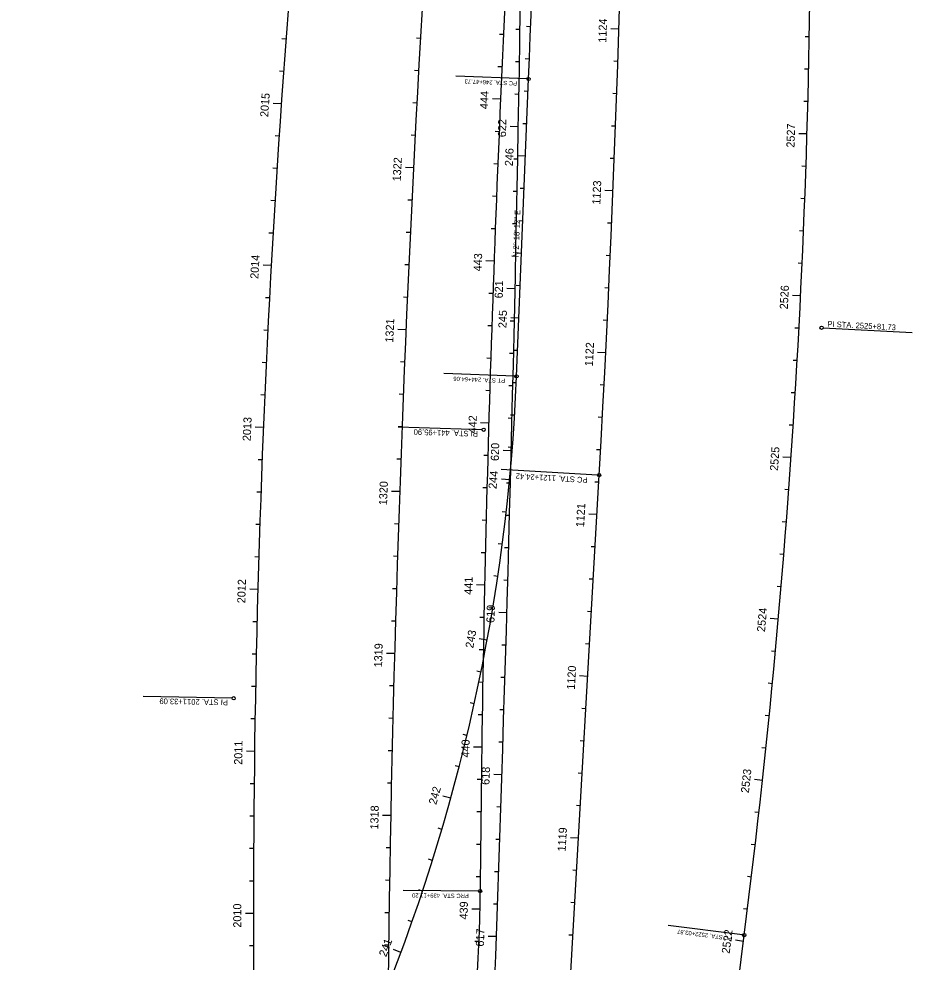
# Model space of a CAD drawing. Extents: x 919452 to 931278, y 583254 to 665650.
# Drawn here: x 928794 to 929346, y 637530 to 638112 of the extents above; entities that cross this region are included whole.
import ezdxf

# ---------------------------------------------------------------- set-up
doc = ezdxf.new("R2010")
doc.units = 0
for name, color, linetype in [('LaneLine', 7, 'Continuous'), ('PMStripe24W', 7, 'Continuous'), ('Scratch1_dp', 7, 'Continuous'), ('ScratchEle_dp', 7, 'Continuous'), ('ShldrHatch', 7, 'Continuous'), ('TollReader', 7, 'Continuous')]:
    doc.layers.add(name, color=color, linetype=linetype)

msp = doc.modelspace()

# ---------------------------------------------------------------- linework, layer by layer
at = {"layer": 'LaneLine'}
for p, q in [((929107.8, 638074.87), (929063.82, 638076.64)), ((929290.62, 637921.24), (929345.52, 637918.33)), ((929100.42, 637891.34), (929056.57, 637893.11)), ((929080.12, 637858.38), (929028.39, 637859.87)), ((929151.39, 637830.41), (929091.99, 637833.78)), ((928925.82, 637692.64), (928870.93, 637693.63)), ((929077.93, 637573.66), (929031.41, 637574.02)), ((929240.92, 637546.59), (929195.04, 637552.42))]:
    msp.add_line(p, q, dxfattribs=at)
for centre in [(929108.8, 638074.83), (929289.62, 637921.3), (929101.42, 637891.3), (929081.12, 637858.35), (929152.38, 637830.35), (928926.82, 637692.63), (929078.93, 637573.66), (929241.91, 637546.46)]:
    msp.add_circle(centre, 1, dxfattribs=at)
at = {"layer": 'Scratch1_dp'}
for p, q in [((929103.52, 638105.32), (929101.02, 638105.36)), ((929110.06, 638107.07), (929107.56, 638107.16)), ((928959.04, 638099.35), (928956.55, 638099.53)), ((929042.08, 638099.86), (929039.58, 638100)), ((929093.34, 638102.23), (929090.84, 638102.35)), ((929282.08, 638100.87), (929279.58, 638100.91)), ((929092.42, 638082.25), (929089.92, 638082.36)), ((929103.19, 638085.32), (929100.69, 638085.36)), ((929109.29, 638087.08), (929106.79, 638087.18)), ((929163.91, 638085.67), (929161.41, 638085.75)), ((928957.58, 638079.4), (928955.09, 638079.58)), ((929040.97, 638079.89), (929038.47, 638080.03)), ((929281.68, 638080.87), (929279.18, 638080.92)), ((929102.85, 638065.32), (929100.35, 638065.37)), ((929108.49, 638067.1), (929105.99, 638067.2)), ((929163.22, 638065.68), (929160.73, 638065.77)), ((929039.88, 638059.92), (929037.39, 638060.05)), ((929281.2, 638060.88), (929278.7, 638060.94)), ((929107.68, 638047.11), (929105.19, 638047.22)), ((929090.67, 638042.29), (929088.17, 638042.4)), ((929162.5, 638045.69), (929160, 638045.78)), ((928954.82, 638039.49), (928952.33, 638039.66)), ((929038.83, 638039.95), (929036.33, 638040.08)), ((929102.11, 638025.33), (929099.61, 638025.38)), ((929161.74, 638025.71), (929159.24, 638025.8)), ((928953.53, 638019.54), (928951.03, 638019.69)), ((929089.83, 638022.31), (929087.33, 638022.41)), ((929280.01, 638020.89), (929277.51, 638020.98)), ((929106.08, 638007.15), (929103.58, 638007.25)), ((929089.03, 638002.32), (929086.53, 638002.42)), ((929101.72, 638005.33), (929099.22, 638005.38)), ((929279.3, 638000.91), (929276.8, 638001)), ((928952.29, 637999.57), (928949.79, 637999.73)), ((929036.82, 638000), (929034.32, 638000.12)), ((929101.32, 637985.34), (929098.82, 637985.39)), ((929105.27, 637987.16), (929102.78, 637987.26)), ((929160.11, 637985.74), (929157.61, 637985.85)), ((928951.1, 637979.61), (928948.61, 637979.75)), ((929035.86, 637980.02), (929033.36, 637980.14)), ((929088.26, 637982.34), (929085.76, 637982.43)), ((929278.51, 637980.92), (929276.01, 637981.03)), ((929100.9, 637965.34), (929098.41, 637965.39)), ((929104.47, 637967.18), (929101.97, 637967.28)), ((929159.24, 637965.76), (929156.74, 637965.87)), ((929034.93, 637960.04), (929032.43, 637960.16)), ((929277.64, 637960.94), (929275.14, 637961.05)), ((929086.8, 637942.36), (929084.3, 637942.45)), ((929103.67, 637947.2), (929101.17, 637947.3)), ((929158.33, 637945.78), (929155.84, 637945.89)), ((928948.9, 637939.67), (928946.4, 637939.8)), ((929034.02, 637940.06), (929031.53, 637940.18)), ((929100.03, 637925.35), (929097.53, 637925.41)), ((929157.39, 637925.8), (929154.89, 637925.92)), ((928947.88, 637919.7), (928945.38, 637919.82)), ((929086.11, 637922.38), (929083.61, 637922.46)), ((929275.67, 637920.99), (929273.17, 637921.12)), ((929102.06, 637907.23), (929099.56, 637907.33)), ((929085.46, 637902.39), (929082.96, 637902.47)), ((929099.57, 637905.36), (929097.07, 637905.41)), ((928946.92, 637899.72), (928944.42, 637899.84)), ((929032.31, 637900.1), (929029.82, 637900.2)), ((929274.57, 637901.02), (929272.07, 637901.16)), ((929099.1, 637885.36), (929096.6, 637885.42)), ((929101.25, 637887.24), (929098.75, 637887.35)), ((929155.4, 637885.85), (929152.9, 637885.98)), ((928946.01, 637879.74), (928943.51, 637879.85)), ((929031.5, 637880.12), (929029.01, 637880.22)), ((929084.83, 637882.4), (929082.33, 637882.47)), ((929273.39, 637881.05), (929270.89, 637881.21)), ((929100.2, 637867.27), (929097.7, 637867.42)), ((929098.62, 637865.37), (929096.12, 637865.43)), ((929154.35, 637865.88), (929151.85, 637866.01)), ((929272.13, 637861.09), (929269.63, 637861.26)), ((929030.72, 637860.13), (929028.23, 637860.23)), ((929098.81, 637847.32), (929096.31, 637847.52)), ((929153.26, 637845.91), (929150.76, 637846.05)), ((928944.36, 637839.77), (928941.86, 637839.87)), ((929029.98, 637840.15), (929027.48, 637840.24)), ((929083.67, 637842.41), (929081.17, 637842.48)), ((929152.13, 637825.94), (929149.64, 637826.08)), ((928943.62, 637819.79), (928941.12, 637819.88)), ((929083.13, 637822.42), (929080.63, 637822.49)), ((929097.6, 637825.38), (929095.1, 637825.45)), ((929269.38, 637821.19), (929266.88, 637821.37)), ((929082.63, 637802.43), (929080.13, 637802.49)), ((929094.98, 637807.51), (929092.5, 637807.79)), ((929097.07, 637805.39), (929094.57, 637805.45)), ((928942.93, 637799.8), (928940.43, 637799.88)), ((929028.57, 637800.17), (929026.07, 637800.26)), ((929267.89, 637801.24), (929265.39, 637801.44)), ((929092.55, 637787.65), (929090.07, 637787.98)), ((929096.53, 637785.39), (929094.03, 637785.46)), ((929149.86, 637786), (929147.37, 637786.15)), ((928942.3, 637779.81), (928939.8, 637779.89)), ((929027.91, 637780.18), (929025.41, 637780.26)), ((929082.15, 637782.43), (929079.65, 637782.49)), ((929266.32, 637781.31), (929263.82, 637781.51)), ((929089.78, 637767.85), (929087.31, 637768.22)), ((929095.98, 637765.4), (929093.48, 637765.47)), ((929148.73, 637766.04), (929146.23, 637766.18)), ((929027.28, 637760.19), (929024.78, 637760.27)), ((929264.67, 637761.37), (929262.18, 637761.58)), ((929086.66, 637748.09), (929084.2, 637748.5)), ((929147.59, 637746.07), (929145.1, 637746.21)), ((928941.21, 637739.83), (928938.71, 637739.89)), ((929026.68, 637740.2), (929024.18, 637740.27)), ((929081.28, 637742.44), (929078.78, 637742.49)), ((929080.89, 637722.45), (929078.39, 637722.49)), ((929094.82, 637725.42), (929092.32, 637725.49)), ((929146.46, 637726.1), (929143.96, 637726.24)), ((929261.14, 637721.53), (929258.65, 637721.76)), ((928940.74, 637719.83), (928938.24, 637719.88)), ((929079.4, 637708.76), (929076.95, 637709.26)), ((929094.23, 637705.43), (929091.73, 637705.5)), ((928940.33, 637699.83), (928937.83, 637699.88)), ((929025.58, 637700.22), (929023.08, 637700.28)), ((929080.53, 637702.45), (929078.03, 637702.49)), ((929259.26, 637701.62), (929256.77, 637701.86)), ((929075.26, 637689.19), (929072.82, 637689.73)), ((929144.19, 637686.16), (929141.69, 637686.31)), ((929025.07, 637680.22), (929022.57, 637680.28)), ((929080.2, 637682.45), (929077.71, 637682.49)), ((929093.61, 637685.44), (929091.11, 637685.51)), ((929257.3, 637681.71), (929254.81, 637681.96)), ((928939.98, 637679.84), (928937.48, 637679.88)), ((929070.78, 637669.7), (929068.35, 637670.28)), ((929092.99, 637665.45), (929090.49, 637665.53)), ((929143.05, 637666.2), (929140.56, 637666.34)), ((929024.59, 637660.23), (929022.09, 637660.29)), ((929255.27, 637661.82), (929252.78, 637662.08)), ((929065.97, 637650.29), (929063.54, 637650.91)), ((929141.92, 637646.23), (929139.42, 637646.37)), ((928939.44, 637639.84), (928936.94, 637639.87)), ((929024.15, 637640.23), (929021.65, 637640.29)), ((929079.63, 637642.46), (929077.14, 637642.49)), ((929079.39, 637622.46), (929076.89, 637622.49)), ((929091.7, 637625.47), (929089.2, 637625.55)), ((929140.78, 637626.26), (929138.29, 637626.4)), ((929250.96, 637622.05), (929248.48, 637622.33)), ((928939.25, 637619.84), (928936.75, 637619.86)), ((929055.33, 637611.73), (929052.93, 637612.44)), ((929091.03, 637605.48), (929088.53, 637605.56)), ((928939.12, 637599.84), (928936.62, 637599.86)), ((929023.35, 637600.24), (929020.85, 637600.29)), ((929079.18, 637602.46), (929076.68, 637602.48)), ((929248.69, 637602.18), (929246.21, 637602.47)), ((929049.51, 637592.6), (929047.12, 637593.35)), ((929079, 637582.46), (929076.5, 637582.48)), ((929090.35, 637585.49), (929087.85, 637585.58)), ((929138.51, 637586.33), (929136.02, 637586.47)), ((929246.35, 637582.32), (929243.86, 637582.62)), ((928939.05, 637579.84), (928936.55, 637579.85)), ((929022.99, 637580.25), (929020.49, 637580.29)), ((929043.36, 637573.57), (929040.98, 637574.36)), ((929089.65, 637565.5), (929087.15, 637565.59)), ((929137.38, 637566.36), (929134.88, 637566.5)), ((929022.66, 637560.25), (929020.16, 637560.29)), ((929243.92, 637562.47), (929241.44, 637562.77)), ((929036.88, 637554.65), (929034.52, 637555.48)), ((929136.24, 637546.39), (929133.75, 637546.53)), ((929078.22, 637542.47), (929075.72, 637542.56)), ((928939.06, 637539.84), (928936.56, 637539.84)), ((929022.37, 637540.25), (929019.87, 637540.28))]:
    msp.add_line(p, q, dxfattribs=at)
at = {"layer": 'ScratchEle_dp'}
for p, q in [((929101.42, 637891.3), (929108.8, 638074.83)), ((929063.91, 636273.75), (929152.38, 637830.35)), ((929141.47, 636757.31), (929241.91, 637546.46))]:
    msp.add_line(p, q, dxfattribs=at)
for centre, radius, start, end in [((918208.05, 638452.43), 10962, 356.746791, 3.806041), ((914272.82, 638671.54), 14847.97, 357.696753, 0.946314), ((900459.43, 638571.38), 28647.89, 355.955427, 0.622371), ((942221.08, 637355.55), 13200, 175.794488, 180.562502), ((924158.91, 638193.39), 5124, 352.74679, 1.18191), ((942581.4, 637470.03), 13502.86, 177.14455, 179.560307), ((936146.52, 637562.53), 7207.49, 175.47906, 182.456288), ((927949.43, 637937.64), 1152.92, 317.11857, 357.69675), ((928044.2, 637581.6), 1034.77, 344.85215, 359.56031)]:
    msp.add_arc(centre, radius, start, end, dxfattribs=at)
at = {"layer": 'TollReader'}
for p, q in [((929164.56, 638105.66), (929159.57, 638105.81)), ((928956.18, 638059.45), (928951.19, 638059.79)), ((929091.53, 638062.27), (929086.53, 638062.49)), ((929102.49, 638045.33), (929097.49, 638045.42)), ((929280.64, 638040.88), (929275.65, 638041.03)), ((929106.88, 638027.13), (929101.88, 638027.33)), ((929037.81, 638019.97), (929032.82, 638020.23)), ((929160.94, 638005.72), (929155.95, 638005.92)), ((928949.97, 637959.64), (928944.98, 637959.92)), ((929087.51, 637962.35), (929082.52, 637962.53)), ((929100.47, 637945.35), (929095.48, 637945.46)), ((929276.69, 637940.96), (929271.7, 637941.21)), ((929102.86, 637927.21), (929097.87, 637927.41)), ((929033.15, 637920.08), (929028.16, 637920.3)), ((929156.41, 637905.82), (929151.42, 637906.07)), ((929084.24, 637862.41), (929079.24, 637862.55)), ((928945.16, 637859.76), (928940.16, 637859.96)), ((929098.12, 637845.37), (929093.12, 637845.5)), ((929270.79, 637841.14), (929265.8, 637841.48)), ((929097.07, 637827.4), (929092.09, 637827.87)), ((929029.26, 637820.16), (929024.26, 637820.34)), ((929151, 637805.97), (929146.01, 637806.25)), ((929081.7, 637762.44), (929076.7, 637762.55)), ((928941.73, 637759.82), (928936.73, 637759.96)), ((929095.41, 637745.41), (929090.41, 637745.55)), ((929262.94, 637741.45), (929257.96, 637741.89)), ((929083.2, 637728.39), (929078.29, 637729.3)), ((929026.11, 637720.21), (929021.12, 637720.35)), ((929145.32, 637706.13), (929140.33, 637706.42)), ((928939.68, 637659.84), (928934.68, 637659.91)), ((929079.91, 637662.45), (929074.91, 637662.53)), ((929092.35, 637645.46), (929087.35, 637645.62)), ((929253.15, 637641.93), (929248.18, 637642.47)), ((929060.81, 637630.96), (929055.99, 637632.29)), ((929023.73, 637620.24), (929018.73, 637620.34)), ((929139.65, 637606.29), (929134.66, 637606.58)), ((928939.03, 637559.84), (928934.03, 637559.84)), ((929078.79, 637562.46), (929073.79, 637562.55)), ((929088.94, 637545.52), (929083.95, 637545.69)), ((929241.42, 637542.62), (929236.46, 637543.25)), ((929030.07, 637535.84), (929025.38, 637537.58))]:
    msp.add_line(p, q, dxfattribs=at)

# ---------------------------------------------------------------- texts
at = {"layer": 'LaneLine'}
for s, height, rotation, p in [('PC STA. 246+47.73', 2.625, 177.69675, (929101.73, 638073.36)), ('PI STA. 2525+81.73', 3.5, 356.96435, (929293.16, 637921.99)), ('PT STA. 244+64.06', 2.625, 177.69675, (929094.35, 637889.84)), ('PI STA. 441+95.90', 3.5, 178.35243, (929077.59, 637857.58)), ('PC STA. 1121+24.42', 3.5, 176.74679, (929145.3, 637829)), ('PI STA. 2011+33.09', 3.5, 178.96767, (928923.3, 637691.81)), ('PRC STA. 439+11.20', 2.625, 179.56031, (929071.92, 637571.96)), ('PC STA. 2522+03.87', 2.625, 172.74679, (929234.75, 637545.61))]:
    msp.add_text(s, height=height, rotation=rotation, dxfattribs=at).set_placement(p)
at = {"layer": 'PMStripe24W'}
msp.add_text('N 2%%d 18\' 12" E', height=3.5, rotation=87.69675, dxfattribs=at).set_placement((929102.62, 637964.83))
at = {"layer": 'ShldrHatch'}
for s, rotation, p in [('1124', 88.1872, (929156.79, 638097.17)), ('2015', 86.04664, (928948.09, 638051.18)), ('444', 87.4862, (929083.75, 638056.12)), ('622', 88.94782, (929094.87, 638038.88)), ('2527', 88.29446, (929272.89, 638032.39)), ('246', 87.69675, (929099.12, 638020.9)), ('1322', 87.11477, (929029.87, 638011.53)), ('1123', 87.66452, (929153.09, 637997.2)), ('2014', 86.84158, (928942, 637951.34)), ('443', 87.91052, (929079.78, 637956.04)), ('621', 88.74782, (929092.84, 637939.38)), ('2526', 87.17628, (929268.77, 637932.56)), ('245', 87.69675, (929095.1, 637920.95)), ('1321', 87.54883, (929025.3, 637912.03)), ('1122', 87.14184, (929148.48, 637897.38)), ('442', 88.33484, (929076.55, 637856.04)), ('2013', 87.63653, (928937.3, 637851.24)), ('620', 88.54782, (929090.45, 637839.04)), ('2525', 86.0581, (929262.7, 637832.86)), ('244', 84.51303, (929088.98, 637821.66)), ('1320', 87.98289, (929021.45, 637811.66)), ('1121', 86.74679, (929143.03, 637798.03)), ('2012', 88.43148, (928933.99, 637751.2)), ('441', 88.75917, (929074.07, 637756.47)), ('619', 88.34782, (929087.72, 637739.1)), ('2524', 84.93991, (929254.7, 637733.41)), ('243', 79.54338, (929074.63, 637723.28)), ('1319', 88.41695, (929018.38, 637711.64)), ('1120', 86.74679, (929137.34, 637697.8)), ('2011', 89.22643, (928932.07, 637651.56)), ('440', 89.18349, (929072.31, 637656.04)), ('618', 88.14782, (929084.64, 637639.13)), ('2523', 83.82173, (929244.74, 637633.95)), ('242', 74.57374, (929051.83, 637626.61)), ('1318', 88.85101, (929016.06, 637611.57)), ('1119', 86.74679, (929131.66, 637597.96)), ('2010', 90.02137, (928931.53, 637551.07)), ('439', 88.94038, (929071.17, 637556.07)), ('617', 87.94782, (929081.22, 637539.32)), ('2522', 82.74679, (929232.87, 637534.81)), ('241', 69.6041, (929020.9, 637532.7))]:
    msp.add_text(s, height=5, rotation=rotation, dxfattribs=at).set_placement(p)

doc.saveas('drawing.dxf')
